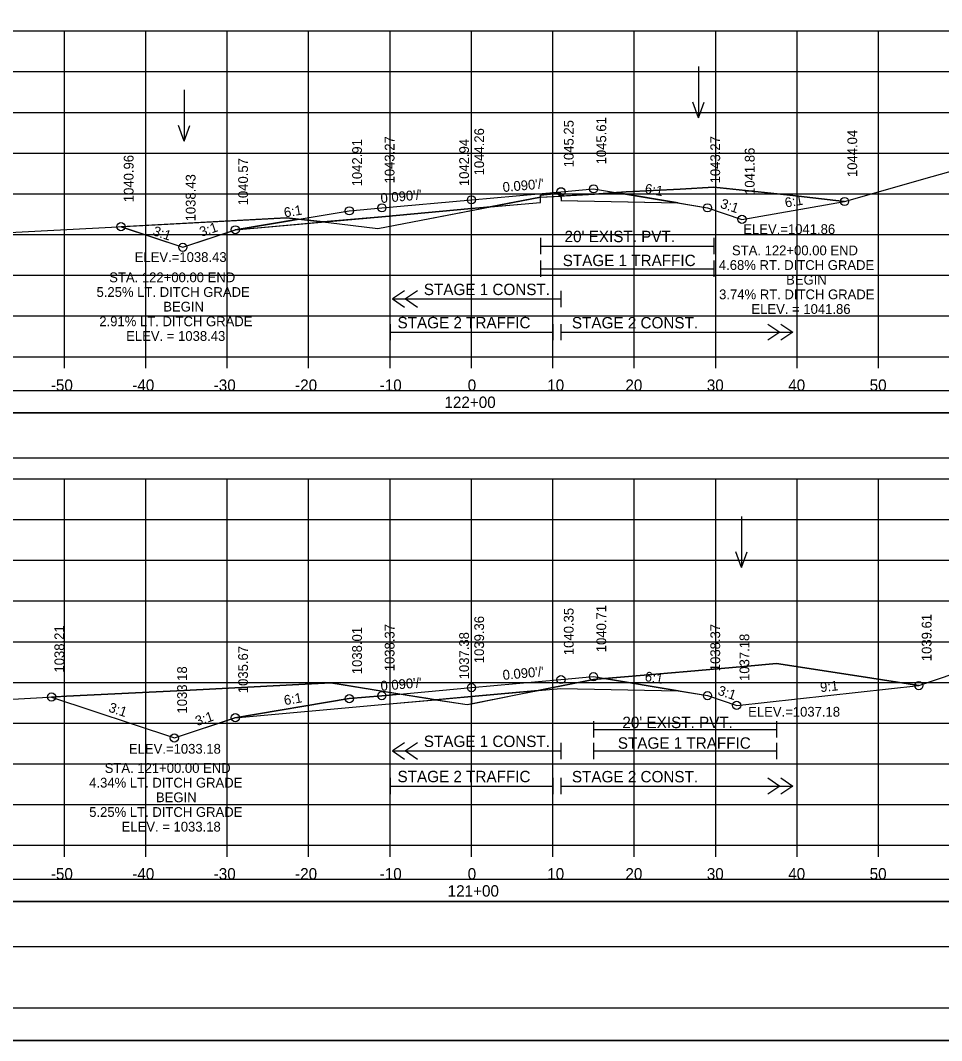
# Model space of a CAD drawing. Extents: x 1370565 to 1374448, y 301010 to 304637.
# Drawn here: x 1370679.6 to 1370792.8, y 303357.2 to 303482.5 of the extents above; entities that cross this region are included whole.
import ezdxf

# ---------------------------------------------------------------- set-up
doc = ezdxf.new("R2010")
doc.units = 0
for name, color, linetype in [('Default', 7, 'Continuous'), ('R_Alt Surface', 7, 'Continuous'), ('R_Axis', 7, 'Continuous'), ('R_Axis Annot', 7, 'Continuous'), ('R_Border', 7, 'Continuous'), ('R_Contours', 7, 'Continuous'), ('R_Drive', 7, 'Continuous'), ('R_Exist Surface', 7, 'Continuous'), ('R_Fin Surface', 7, 'Continuous'), ('R_Grid', 7, 'Continuous'), ('R_No Plot', 7, 'Continuous'), ('R_Water', 7, 'Continuous'), ('R_Water Annot', 7, 'Continuous'), ('R_Xsect Elev', 7, 'Continuous'), ('R_Xsect Slope', 7, 'Continuous')]:
    doc.layers.add(name, color=color, linetype=linetype)

msp = doc.modelspace()

# ---------------------------------------------------------------- linework, layer by layer
at = {"layer": 'Default'}
msp.add_lwpolyline([(1370585.82, 303368.77), (1370884.24, 303368.77), (1370884.24, 303374.29), (1370585.82, 303374.29)], close=True, dxfattribs=at)
at = {"layer": 'R_Alt Surface'}
for points in [[(1370705.99, 303456.75), (1370724.03, 303458.38), (1370735.03, 303459.37), (1370743.52, 303460.12), (1370743.52, 303461.04), (1370746.03, 303461.27), (1370746.04, 303460.35), (1370746.03, 303460.36), (1370760.41, 303460.07)], [(1370743.52, 303455.77), (1370743.52, 303453.77)], [(1370764.8, 303455.77), (1370764.8, 303453.77)], [(1370743.52, 303454.77), (1370764.8, 303454.77)], [(1370743.52, 303452.99), (1370743.52, 303450.99)], [(1370764.8, 303452.99), (1370764.8, 303450.99)], [(1370743.52, 303451.99), (1370764.8, 303451.99)], [(1370726.82, 303449.28), (1370725.32, 303448.28), (1370726.82, 303447.28)], [(1370728.42, 303449.28), (1370726.92, 303448.28), (1370728.42, 303447.28)], [(1370725.32, 303448.28), (1370746.03, 303448.28)], [(1370725.03, 303445.2), (1370725.03, 303443.2)], [(1370725.03, 303444.2), (1370745.03, 303444.2)], [(1370745.03, 303445.2), (1370745.03, 303443.2)], [(1370746.03, 303445.2), (1370746.03, 303443.2)], [(1370746.03, 303445.2), (1370746.03, 303443.2)], [(1370746.03, 303444.2), (1370774.52, 303444.2)], [(1370771.42, 303445.2), (1370772.92, 303444.2), (1370771.42, 303443.2)], [(1370773.02, 303445.2), (1370774.52, 303444.2), (1370773.02, 303443.2)], [(1370705.98, 303396.85), (1370724.03, 303398.48), (1370735.03, 303399.47), (1370746.03, 303400.46), (1370760.41, 303400.17)], [(1370726.82, 303393.78), (1370725.32, 303392.78), (1370726.82, 303391.78)], [(1370725.32, 303392.78), (1370746.03, 303392.78)], [(1370728.42, 303393.78), (1370726.92, 303392.78), (1370728.42, 303391.78)], [(1370725.03, 303389.46), (1370725.03, 303387.46)], [(1370745.03, 303389.46), (1370745.03, 303387.46)], [(1370746.03, 303389.46), (1370746.03, 303387.46)], [(1370746.03, 303389.46), (1370746.03, 303387.46)], [(1370771.42, 303389.46), (1370772.92, 303388.46), (1370771.42, 303387.46)], [(1370773.02, 303389.46), (1370774.52, 303388.46), (1370773.02, 303387.46)], [(1370725.03, 303388.46), (1370745.03, 303388.46)], [(1370746.03, 303388.46), (1370774.52, 303388.46)]]:
    msp.add_lwpolyline(points, dxfattribs=at)
at = {"layer": 'R_Axis'}
for p, q in [((1370585.03, 303441.19), (1370885.03, 303441.19)), ((1370685.03, 303439.79), (1370685.03, 303441.19)), ((1370695.03, 303439.79), (1370695.03, 303441.19)), ((1370705.03, 303439.79), (1370705.03, 303441.19)), ((1370715.03, 303439.79), (1370715.03, 303441.19)), ((1370725.03, 303439.79), (1370725.03, 303441.19)), ((1370735.03, 303439.79), (1370735.03, 303441.19)), ((1370745.03, 303439.79), (1370745.03, 303441.19)), ((1370755.03, 303439.79), (1370755.03, 303441.19)), ((1370765.03, 303439.79), (1370765.03, 303441.19)), ((1370775.03, 303439.79), (1370775.03, 303441.19)), ((1370785.03, 303439.79), (1370785.03, 303441.19)), ((1370585.03, 303381.19), (1370885.03, 303381.19)), ((1370685.03, 303379.79), (1370685.03, 303381.19)), ((1370695.03, 303379.79), (1370695.03, 303381.19)), ((1370705.03, 303379.79), (1370705.03, 303381.19)), ((1370715.03, 303379.79), (1370715.03, 303381.19)), ((1370725.03, 303379.79), (1370725.03, 303381.19)), ((1370735.03, 303379.79), (1370735.03, 303381.19)), ((1370745.03, 303379.79), (1370745.03, 303381.19)), ((1370755.03, 303379.79), (1370755.03, 303381.19)), ((1370765.03, 303379.79), (1370765.03, 303381.19)), ((1370775.03, 303379.79), (1370775.03, 303381.19)), ((1370785.03, 303379.79), (1370785.03, 303381.19))]:
    msp.add_line(p, q, dxfattribs=at)
for points in [[(1370746.03, 303449.28), (1370746.03, 303447.28)], [(1370750.01, 303396.43), (1370750.01, 303394.43)], [(1370772.51, 303396.43), (1370772.51, 303394.43)], [(1370750.01, 303395.43), (1370772.51, 303395.43)], [(1370746.03, 303393.78), (1370746.03, 303391.78)], [(1370750.01, 303393.78), (1370750.01, 303391.78)], [(1370750.01, 303392.78), (1370772.51, 303392.78)], [(1370772.51, 303393.78), (1370772.51, 303391.78)]]:
    msp.add_lwpolyline(points, dxfattribs=at)
at = {"layer": 'R_Border'}
msp.add_line((1370893.21, 303361.19), (1370577.03, 303361.19), dxfattribs=at)
at = {"layer": 'R_Contours'}
for p, q in [((1370743.52, 303460.77), (1370737.32, 303459.57)), ((1370743.52, 303460.77), (1370746.03, 303460.91)), ((1370743.52, 303460.12), (1370743.52, 303460.77)), ((1370746.03, 303460.91), (1370746.03, 303461.27)), ((1370760.41, 303460.07), (1370752.83, 303461.33)), ((1370736.51, 303459.5), (1370735.03, 303459.37)), ((1370735.03, 303459.13), (1370736.52, 303459.42)), ((1370735.03, 303459.13), (1370735.03, 303459.37)), ((1370735.03, 303459.37), (1370735.03, 303459.13)), ((1370737.32, 303459.57), (1370736.51, 303459.5)), ((1370736.52, 303459.42), (1370737.32, 303459.57)), ((1370737.32, 303459.57), (1370743.52, 303460.12)), ((1370712.3, 303458.22), (1370692.01, 303457.15)), ((1370713.79, 303458.06), (1370705.99, 303456.75)), ((1370713.79, 303458.06), (1370712.3, 303458.22)), ((1370716.83, 303457.73), (1370713.79, 303458.06)), ((1370705.99, 303456.75), (1370716.83, 303457.73)), ((1370716.83, 303457.73), (1370717.49, 303457.66)), ((1370760.41, 303400.17), (1370751.37, 303401.68)), ((1370743.24, 303400.21), (1370735.03, 303399.47)), ((1370726.24, 303399.76), (1370724.03, 303399.56)), ((1370724.03, 303399.56), (1370726.24, 303399.76)), ((1370735.03, 303399.47), (1370730.61, 303399.07)), ((1370730.61, 303399.07), (1370734.52, 303398.47)), ((1370735.03, 303399.47), (1370735.03, 303398.57)), ((1370735.03, 303398.57), (1370735.03, 303399.47)), ((1370734.52, 303398.47), (1370735.03, 303398.57))]:
    msp.add_line(p, q, dxfattribs=at)
for points in [[(1370780.86, 303460.24), (1370774.14, 303461.02), (1370764.8, 303461.99), (1370760.67, 303461.76), (1370754.02, 303461.41), (1370752.83, 303461.33)], [(1370746.03, 303461.27), (1370743.52, 303461.04), (1370743.52, 303460.77)], [(1370752.83, 303461.33), (1370750.15, 303461.15), (1370746.03, 303460.91)], [(1370746.03, 303460.91), (1370746.04, 303460.35), (1370760.41, 303460.07)], [(1370752.83, 303461.33), (1370760.41, 303460.07), (1370764.03, 303459.47)], [(1370735.03, 303459.37), (1370724.03, 303458.38), (1370716.83, 303457.73)], [(1370717.49, 303457.66), (1370723.54, 303456.94), (1370735.03, 303459.13)], [(1370736.52, 303459.42), (1370736.51, 303459.5)], [(1370736.51, 303459.5), (1370736.52, 303459.42)], [(1370764.03, 303459.47), (1370768.26, 303458.05), (1370780.86, 303460.24)], [(1370692.01, 303457.15), (1370699.59, 303454.62), (1370705.99, 303456.75), (1370713.79, 303458.06)], [(1370789.99, 303400.8), (1370782.92, 303401.92), (1370772.51, 303403.53), (1370768.49, 303403.14), (1370761.52, 303402.53), (1370753.83, 303401.89), (1370751.37, 303401.68)], [(1370751.37, 303401.68), (1370750.01, 303401.56), (1370743.24, 303400.21)], [(1370751.37, 303401.68), (1370760.41, 303400.17), (1370764.03, 303399.57)], [(1370726.24, 303399.76), (1370717.75, 303401.12), (1370699.72, 303400.21), (1370685.28, 303399.5), (1370683.46, 303399.4)], [(1370735.03, 303398.57), (1370741.09, 303399.78), (1370743.24, 303400.21)], [(1370743.24, 303400.21), (1370746.03, 303400.46), (1370760.41, 303400.17)], [(1370764.03, 303399.57), (1370767.61, 303398.37), (1370789.99, 303400.8)], [(1370683.46, 303399.4), (1370698.54, 303394.37), (1370705.98, 303396.85), (1370720.03, 303399.2), (1370724.03, 303399.56)], [(1370724.03, 303399.56), (1370720.03, 303399.2), (1370705.98, 303396.85)], [(1370705.98, 303396.85), (1370724.03, 303398.48), (1370730.61, 303399.07)], [(1370730.61, 303399.07), (1370729.44, 303399.25), (1370726.24, 303399.76)]]:
    msp.add_lwpolyline(points, dxfattribs=at)
at = {"layer": 'R_Drive'}
for points in [[(1370585.82, 303434.29), (1370884.24, 303434.29), (1370884.24, 303436.99), (1370585.82, 303436.99)], [(1370585.82, 303428.77), (1370884.24, 303428.77), (1370884.24, 303434.29), (1370585.82, 303434.29)], [(1370585.82, 303374.29), (1370884.24, 303374.29), (1370884.24, 303376.99), (1370585.82, 303376.99)]]:
    msp.add_lwpolyline(points, close=True, dxfattribs=at)
at = {"layer": 'R_Exist Surface'}
for points in [[(1370661.15, 303455.55), (1370682.19, 303456.63), (1370690.06, 303457.06), (1370712.3, 303458.22), (1370717.49, 303457.66), (1370723.54, 303456.94), (1370736.52, 303459.42), (1370743.52, 303460.77), (1370750.15, 303461.15), (1370754.02, 303461.41), (1370760.67, 303461.76), (1370764.8, 303461.99), (1370774.14, 303461.02), (1370780.86, 303460.24), (1370791.64, 303463.31), (1370798.03, 303465.12)], [(1370666.81, 303398.48), (1370685.28, 303399.5), (1370699.72, 303400.21), (1370717.75, 303401.12), (1370729.44, 303399.25), (1370734.52, 303398.47), (1370741.09, 303399.78), (1370750.01, 303401.56), (1370753.83, 303401.89), (1370761.52, 303402.53), (1370768.49, 303403.14), (1370772.51, 303403.53), (1370782.92, 303401.92), (1370789.99, 303400.8), (1370801.09, 303404.59)]]:
    msp.add_lwpolyline(points, dxfattribs=at)
at = {"layer": 'R_Fin Surface'}
for points in [[(1370691.98, 303457.16), (1370699.59, 303454.62), (1370706.03, 303456.77), (1370720.03, 303459.1), (1370724.03, 303459.46), (1370735.03, 303460.45), (1370746.03, 303461.44), (1370750.03, 303461.8), (1370764.03, 303459.47), (1370768.26, 303458.05), (1370780.86, 303460.24)], [(1370683.46, 303399.4), (1370698.54, 303394.37), (1370706.03, 303396.87), (1370720.03, 303399.2), (1370724.03, 303399.56), (1370735.03, 303400.55), (1370746.03, 303401.54), (1370750.03, 303401.9), (1370764.03, 303399.57), (1370767.61, 303398.37), (1370789.99, 303400.8)]]:
    msp.add_lwpolyline(points, dxfattribs=at)
at = {"layer": 'R_Grid'}
for p, q in [((1370585.03, 303481.19), (1370885.03, 303481.19)), ((1370685.03, 303441.19), (1370685.03, 303481.19)), ((1370695.03, 303441.19), (1370695.03, 303481.19)), ((1370705.03, 303441.19), (1370705.03, 303481.19)), ((1370715.03, 303441.19), (1370715.03, 303481.19)), ((1370725.03, 303441.19), (1370725.03, 303481.19)), ((1370735.03, 303441.19), (1370735.03, 303481.19)), ((1370745.03, 303441.19), (1370745.03, 303481.19)), ((1370755.03, 303441.19), (1370755.03, 303481.19)), ((1370765.03, 303441.19), (1370765.03, 303481.19)), ((1370775.03, 303441.19), (1370775.03, 303481.19)), ((1370785.03, 303441.19), (1370785.03, 303481.19)), ((1370585.03, 303476.19), (1370885.03, 303476.19)), ((1370585.03, 303471.19), (1370885.03, 303471.19)), ((1370585.03, 303466.19), (1370885.03, 303466.19)), ((1370585.03, 303461.19), (1370885.03, 303461.19)), ((1370585.03, 303456.19), (1370885.03, 303456.19)), ((1370585.03, 303451.19), (1370885.03, 303451.19)), ((1370585.03, 303446.19), (1370885.03, 303446.19)), ((1370585.03, 303441.19), (1370885.03, 303441.19)), ((1370585.03, 303426.19), (1370885.03, 303426.19)), ((1370685.03, 303381.19), (1370685.03, 303426.19)), ((1370695.03, 303381.19), (1370695.03, 303426.19)), ((1370705.03, 303381.19), (1370705.03, 303426.19)), ((1370715.03, 303381.19), (1370715.03, 303426.19)), ((1370725.03, 303381.19), (1370725.03, 303426.19)), ((1370735.03, 303381.19), (1370735.03, 303426.19)), ((1370745.03, 303381.19), (1370745.03, 303426.19)), ((1370755.03, 303381.19), (1370755.03, 303426.19)), ((1370765.03, 303381.19), (1370765.03, 303426.19)), ((1370775.03, 303381.19), (1370775.03, 303426.19)), ((1370785.03, 303381.19), (1370785.03, 303426.19)), ((1370585.03, 303421.19), (1370885.03, 303421.19)), ((1370585.03, 303416.19), (1370885.03, 303416.19)), ((1370585.03, 303411.19), (1370885.03, 303411.19)), ((1370585.03, 303406.19), (1370885.03, 303406.19)), ((1370585.03, 303401.19), (1370885.03, 303401.19)), ((1370585.03, 303396.19), (1370885.03, 303396.19)), ((1370585.03, 303391.19), (1370885.03, 303391.19)), ((1370585.03, 303386.19), (1370885.03, 303386.19)), ((1370585.03, 303381.19), (1370885.03, 303381.19))]:
    msp.add_line(p, q, dxfattribs=at)
at = {"layer": 'R_No Plot'}
msp.add_line((1370564.63, 303357.22), (1370897.96, 303357.22), dxfattribs=at)
for points in [[(1370564.62, 303570.55), (1370897.96, 303570.55), (1370897.96, 303357.21), (1370564.62, 303357.21)], [(1370810.95, 303566.65), (1370830.57, 303566.65), (1370830.57, 303556.77), (1370846.68, 303556.77), (1370869.88, 303556.77), (1370869.88, 303524.1), (1370893.09, 303524.1), (1370893.21, 303361.19), (1370577.03, 303361.19), (1370577.03, 303566.65)]]:
    msp.add_lwpolyline(points, close=True, dxfattribs=at)
for centre in [(1370746.03, 303461.44), (1370750.03, 303461.8), (1370735.03, 303460.45), (1370780.86, 303460.24), (1370720.03, 303459.1), (1370724.03, 303459.46), (1370764.03, 303459.47), (1370768.26, 303458.05), (1370691.98, 303457.16), (1370706.03, 303456.77), (1370699.59, 303454.62), (1370746.03, 303401.54), (1370750.03, 303401.9), (1370735.03, 303400.55), (1370789.99, 303400.8), (1370683.46, 303399.4), (1370720.03, 303399.2), (1370724.03, 303399.56), (1370764.03, 303399.57), (1370767.61, 303398.37), (1370706.03, 303396.87), (1370698.54, 303394.37)]:
    msp.add_circle(centre, 0.5, dxfattribs=at)
at = {"layer": 'R_Water Annot'}
for p, q in [((1370762.92, 303476.81), (1370762.92, 303470.53)), ((1370699.73, 303473.96), (1370699.73, 303467.67)), ((1370762.92, 303470.53), (1370762.22, 303472.45)), ((1370762.92, 303470.53), (1370763.62, 303472.45)), ((1370699.73, 303467.67), (1370699.03, 303469.59)), ((1370699.73, 303467.67), (1370700.43, 303469.59)), ((1370768.19, 303421.58), (1370768.19, 303415.29)), ((1370768.19, 303415.29), (1370767.49, 303417.21)), ((1370768.19, 303415.29), (1370768.89, 303417.21))]:
    msp.add_line(p, q, dxfattribs=at)
at = {"layer": 'R_Xsect Elev'}
for p, q in [((1370735.03, 303459.13), (1370735.03, 303469.13)), ((1370735.03, 303398.57), (1370735.03, 303408.57))]:
    msp.add_line(p, q, dxfattribs=at)

# ---------------------------------------------------------------- texts
at = {"layer": 'R_Axis Annot'}
for s, p in [("20' EXIST. PVT.", (1370746.47, 303455.25)), ('-50', (1370683.37, 303436.99)), ('-40', (1370693.37, 303436.99)), ('-30', (1370703.37, 303436.99)), ('-20', (1370713.37, 303436.99)), ('-10', (1370723.76, 303436.99)), ('0', (1370734.57, 303436.99)), ('10', (1370744.34, 303436.99)), ('20', (1370753.94, 303436.99)), ('30', (1370763.94, 303436.99)), ('40', (1370773.94, 303436.99)), ('50', (1370783.94, 303436.99)), ('122+00', (1370731.71, 303434.89)), ("20' EXIST. PVT.", (1370753.57, 303395.58)), ('-50', (1370683.37, 303376.99)), ('-40', (1370693.37, 303376.99)), ('-30', (1370703.37, 303376.99)), ('-20', (1370713.37, 303376.99)), ('-10', (1370723.76, 303376.99)), ('0', (1370734.57, 303376.99)), ('10', (1370744.34, 303376.99)), ('20', (1370753.94, 303376.99)), ('30', (1370763.94, 303376.99)), ('40', (1370773.94, 303376.99)), ('50', (1370783.94, 303376.99)), ('121+00', (1370732.11, 303374.89))]:
    msp.add_text(s, height=1.4, dxfattribs=at).set_placement(p)
at = {"layer": 'R_Water'}
for s, p in [('STAGE 1 TRAFFIC', (1370746.24, 303452.31)), ('STAGE 1 CONST.', (1370729.18, 303448.75)), ('STAGE 2 TRAFFIC', (1370725.95, 303444.67)), ('STAGE 2 CONST.', (1370747.37, 303444.66)), ('STAGE 1 CONST.', (1370729.18, 303393.26)), ('STAGE 1 TRAFFIC', (1370753.01, 303393.05)), ('STAGE 2 TRAFFIC', (1370725.95, 303388.94)), ('STAGE 2 CONST.', (1370747.37, 303388.92))]:
    msp.add_text(s, height=1.4, dxfattribs=at).set_placement(p)
at = {"layer": 'R_Xsect Elev'}
for s, p in [('1045.61', (1370751.58, 303464.8)), ('1044.26', (1370736.58, 303463.45)), ('1045.25', (1370747.58, 303464.44)), ('1042.91', (1370721.58, 303462.1)), ('1043.27', (1370725.58, 303462.46)), ('1042.94', (1370734.73, 303462.13)), ('1043.27', (1370765.58, 303462.47)), ('1044.04', (1370782.41, 303463.24)), ('1041.86', (1370769.81, 303461.05)), ('1040.96', (1370693.53, 303460.16)), ('1040.57', (1370707.58, 303459.77)), ('1038.43', (1370701.14, 303457.8)), ('1040.35', (1370747.58, 303404.54)), ('1040.71', (1370751.58, 303404.9)), ('1039.36', (1370736.58, 303403.55)), ('1039.61', (1370791.54, 303403.8)), ('1038.21', (1370685.01, 303402.4)), ('1038.01', (1370721.58, 303402.2)), ('1038.37', (1370725.58, 303402.56)), ('1038.37', (1370765.58, 303402.57)), ('1037.38', (1370734.73, 303401.57)), ('1037.18', (1370769.16, 303401.37)), ('1035.67', (1370707.58, 303399.87)), ('1033.18', (1370700.09, 303397.37))]:
    msp.add_text(s, height=1.2, rotation=90, dxfattribs=at).set_placement(p)
for s, p in [('ELEV.=1041.86', (1370768.42, 303456.25)), ('ELEV.=1038.43', (1370693.67, 303452.82)), ('STA. 122+00.00 END', (1370767.03, 303453.64)), ('4.68% RT. DITCH GRADE', (1370765.42, 303451.84)), ('STA. 122+00.00 END', (1370690.54, 303450.33)), ('BEGIN', (1370773.68, 303450.04)), ('5.25% LT. DITCH GRADE', (1370688.98, 303448.53)), ('3.74% RT. DITCH GRADE', (1370765.45, 303448.24)), ('BEGIN', (1370697.18, 303446.73)), ('ELEV. = 1041.86', (1370769.42, 303446.44)), ('2.91% LT. DITCH GRADE', (1370689.32, 303444.93)), ('ELEV. = 1038.43', (1370692.62, 303443.13)), ('ELEV.=1037.18', (1370769.02, 303396.99)), ('ELEV.=1033.18', (1370692.96, 303392.44)), ('STA. 121+00.00 END', (1370689.98, 303390.08)), ('4.34% LT. DITCH GRADE', (1370688.08, 303388.28)), ('BEGIN', (1370696.28, 303386.48)), ('5.25% LT. DITCH GRADE', (1370688.08, 303384.68)), ('ELEV. = 1033.18', (1370692.06, 303382.88))]:
    msp.add_text(s, height=1.2, dxfattribs=at).set_placement(p)
at = {"layer": 'R_Xsect Slope'}
for s, rotation, p in [("0.090'/'", 5.1428, (1370738.92, 303461.4)), ("0.090'/'", 5.1428, (1370723.92, 303460.05)), ('6:1', 350.5358, (1370756.26, 303461.27)), ('3:1', 341.5651, (1370765.51, 303459.5)), ('6:1', 9.8263, (1370773.63, 303459.49)), ('6:1', 9.4642, (1370712.1, 303458.28)), ('3:1', 341.5668, (1370695.8, 303456.13)), ('3:1', 18.4349, (1370701.86, 303455.9)), ("0.090'/'", 5.1428, (1370738.92, 303401.5)), ("0.090'/'", 5.1428, (1370723.92, 303400.15)), ('6:1', 350.5377, (1370756.26, 303401.37)), ('3:1', 341.5651, (1370765.19, 303399.71)), ('9:1', 6.1895, (1370777.92, 303399.99)), ('6:1', 9.4623, (1370712.1, 303398.39)), ('3:1', 341.5668, (1370690.37, 303397.63)), ('3:1', 18.4349, (1370701.34, 303395.83))]:
    msp.add_text(s, height=1.2, rotation=rotation, dxfattribs=at).set_placement(p)

doc.saveas('drawing.dxf')
